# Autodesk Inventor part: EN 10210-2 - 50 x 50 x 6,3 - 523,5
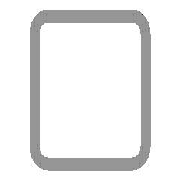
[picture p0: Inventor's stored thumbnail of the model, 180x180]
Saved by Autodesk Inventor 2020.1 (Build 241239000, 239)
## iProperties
IsCustomPart: 1
_CCFamilyMember: 18
_CCFamilyDisplayName: DIN EN 10210-2 (USAS B17.1 quadratisch) - Rohrleitung — In Klammern angegebene Größen wurden aufgehoben
_FrameMemberDoc: Frame Member File
_Version: 15.0.0
_GetPNFromCC: 1
Created: 2019-01
Part Number: EN 10210-2 - 50 x 50 x 6,3 - 523,5
Material: Stahl, weich
Description: Rohrleitung
Document SubType Name: Modeling
Standard: DIN
Designer: lutzd
Standard Revision: 2006-07
Standards Organization: DIN
Language: de-DE
Size Designation: 50 x 50 x 6,3
Categories: <MemberInstance><Categories><Category DisplayName="Profile" InternalName="089c4875-fa83-4c05-b084-43b9cc11f5ed" Mnemonic="GRDR"><CategoryParameter DisplayName="
Stock Number: 50 x 50 x 6,3
Mass: 4343.64 g
Surface Area: 1712.26 cm^2
Volume: 553.33 cm^3
Density: 7.85 g/cm^3
Appearance: Halbpoliert
G_L: 523,500 mm
G_W: 50,000 mm
G_H: 50,000 mm
DocNumber: ADSK-014133
Folder: .
Dimensions: 50x50x523,5 mm
Mass: 4,344 kg
+A91945D6-CAAB-48F4-B8A4-A76AA0C86CF7+SCHNITTDETAIL1: Schnittwinkel 90,00 grd
Title: Profil-Bauteil
Author: lutzd
Revision Number: -
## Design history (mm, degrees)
node "Startebene"
node "Endebene"
sketch "Skizze"
  geometry: L1 (-25, -15.55)-(-25, 15.55); L2 (-15.55, 25)-(15.55, 25); L3 (25, 15.55)-(25, -15.55); L4 (15.55, -25)-(-15.55, -25); L5 (-12.4, 18.7)-(12.4, 18.7); L6 (18.7, 12.4)-(18.7, -12.4); L7 (12.4, -18.7)-(-12.4, -18.7); L8 (-18.7, -12.4)-(-18.7, 12.4); L9 (0, 37.74)-(0, -37.74) reference; L10 (-37.74, 0)-(37.74, 0) reference; A1 r 9.45 centre (-15.55, -15.55) between (-25, -15.55) and (-15.55, -25); A2 r 9.45 centre (-15.55, 15.55) between (-15.55, 25) and (-25, 15.55); A3 r 9.45 centre (15.55, 15.55) between (25, 15.55) and (15.55, 25); A4 r 9.45 centre (15.55, -15.55) between (15.55, -25) and (25, -15.55); A5 r 6.3 centre (-12.4, -12.4) between (-18.7, -12.4) and (-12.4, -18.7); A6 r 6.3 centre (-12.4, 12.4) between (-12.4, 18.7) and (-18.7, 12.4); A7 r 6.3 centre (12.4, 12.4) between (18.7, 12.4) and (12.4, 18.7); A8 r 6.3 centre (12.4, -12.4) between (12.4, -18.7) and (18.7, -12.4)
  constraints: 16 end point, 16 point on circle, 16 tangent, 8 centre point, 6 equal radius, 4 parallel, 2 perpendicular, 2 other
  dimensions: "d7" = 9.45 radius of A1 (= G_IR); "d10" = 50 distance between parallel lines of L2 L4 (= G_H); "d11" = 50 distance between parallel lines of L1 L3 (= G_W); "d12" = 6.3 distance between parallel lines of L3 L6 (= G_T); "d15" = 25 distance between parallel lines of L2 L10 (= 0.5 x d10); "d16" = 25 distance between parallel lines of L9 L3 (= 0.5 x d11); "d19" = 6.3 radius of A5 (= G_T); "d20" = 6.3 distance between parallel lines of L4 L7 (= G_T)
extrude "Körper" new body sketch "Skizze" stored distance "d3" = 523.5 (= G_L); taper "d4" = 0 deg
node "Driven Length"
  sketch "Sketch3"
    geometry: L1 (0, 0)-(10, 0) reference
    constraints: 2 end point, 1 horizontal
  workplane "Work Plane3"
  sketch "Sketch4"
    geometry: L1 (-2, 25)-(12, 25) reference; L2 (-2, 548.5)-(12, 548.5) reference
    dimensions: "d18" = 523.5 distance between parallel lines of L1 L2 (derived)
workplane "Arbeitsebene4"
feature "Trennen1"
sketch "Skizze5"
  geometry: L1 (31.1, 0)-(0, 0) reference; L2 (15.55, 0)-(15.55, 453); 3 further points
  constraints: 2 end point, 1 coincident, 1 midpoint, 1 point on line, 1 vertical
  dimensions: "d21" = 45 distance of point (15.55, 408) point (15.55, 453); "d22" = 408 distance from line of L1 point (15.55, 408)
hole "Bohrung1" sketch "Skizze5" at (15.55, 453), (15.55, 408) diameter "d23" = 6.647; stored, may be unused: countersink angle "d27" = 90 deg, drill point angle "d29" = 118 deg; dims "d24" = 16, "d25" = 4, "d26" = 2, "d28" = 8
sketch "Skizze6"
  geometry: L1 (523.5, 31.1)-(523.5, 0) reference; L2 (523.5, 15.55)-(202.5, 15.55); 3 further points
  constraints: 2 end point, 1 coincident, 1 horizontal, 1 midpoint, 1 point on line
  dimensions: "d30" = 41 distance of point (243.5, 15.55) point (202.5, 15.55); "d31" = 280 distance from line of L1 point (243.5, 15.55)
hole "Bohrung2" sketch "Skizze6" at (202.5, 15.55), (243.5, 15.55) diameter "d32" = 6.647; stored, may be unused: countersink angle "d36" = 90 deg, drill point angle "d38" = 118 deg; dims "d33" = 16, "d34" = 4, "d35" = 2, "d37" = 8
body "Solid1"
other parameters: "G_W" = 50 [user parameter; used in 1 equation term], "G_H" = 50 [user parameter; used in 1 equation term], "G_T" = 6.3 [user parameter; used in 3 equation terms], "G_IR" = 9.45 [user parameter; used in 1 equation term], "G_L" = 523.5 (= d18) [user parameter; used in 1 equation term], "G_OFFSET_START" = -25 [user parameter; used in 1 equation term], "G_OFFSET_END" = 63.5 [user parameter; used in 1 equation term], "d13" = 25 (= -G_OFFSET_START), "d14" = 548.5 (= G_OFFSET_END + B_L), "B_L" = 485 [user parameter; used in 1 equation term], "d17" = 90 deg
